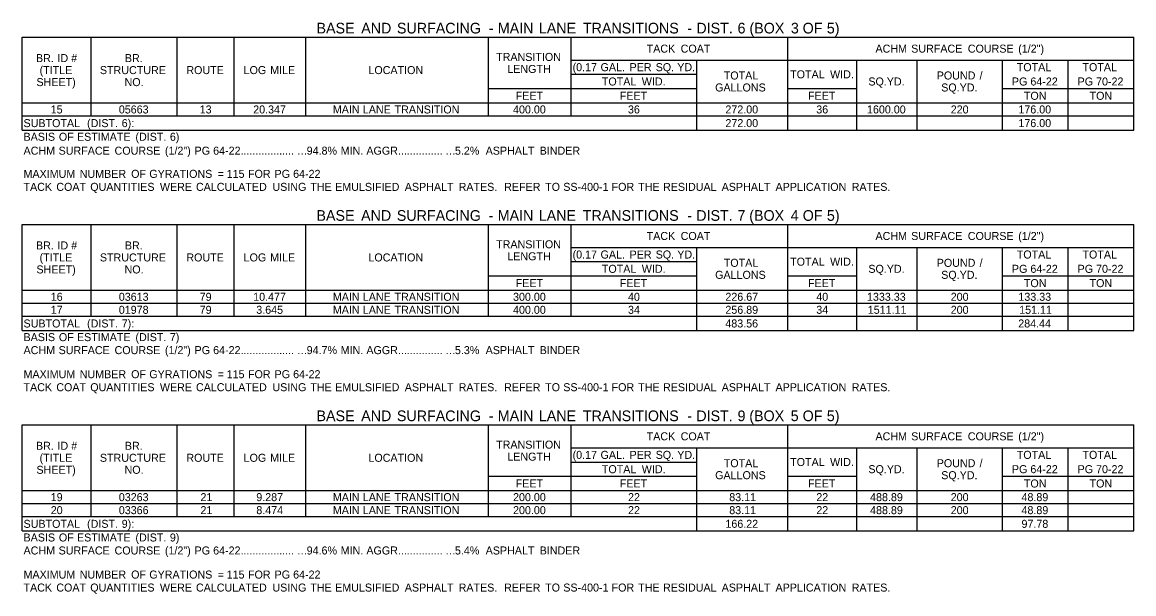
# Model space of a CAD drawing. Extents: x 544255 to 1930787, y -1947044 to 596640.
# Drawn here: x 550281 to 551114, y -1946947 to -1946518 of the extents above; entities that cross this region are included whole.
import ezdxf

# ---------------------------------------------------------------- set-up
doc = ezdxf.new("R2010")
doc.units = 0
doc.layers.add('Default', color=7, linetype='Continuous')

msp = doc.modelspace()

# ---------------------------------------------------------------- linework, layer by layer
at = {"layer": 'Default'}
for p, q in [((550280.78, -1946529.49), (551113.92, -1946529.49)), ((550280.78, -1946599.2), (550280.78, -1946529.49)), ((550332.46, -1946588.47), (550332.46, -1946529.49)), ((550396.81, -1946588.47), (550396.81, -1946529.49)), ((550439.71, -1946588.47), (550439.71, -1946529.49)), ((550493.33, -1946588.47), (550493.33, -1946529.49)), ((550630.32, -1946588.47), (550630.32, -1946529.49)), ((550692.23, -1946588.47), (550692.23, -1946529.49)), ((550692.23, -1946546.55), (550692.23, -1946529.49)), ((550854.57, -1946599.2), (550854.57, -1946529.49)), ((551113.92, -1946599.2), (551113.92, -1946529.49)), ((550692.23, -1946546.55), (551113.92, -1946546.55)), ((550786.32, -1946557.27), (550786.32, -1946546.55)), ((550786.32, -1946599.2), (550786.32, -1946546.55)), ((550906.24, -1946546.55), (550951.58, -1946546.55)), ((550906.24, -1946599.2), (550906.24, -1946546.55)), ((550951.58, -1946599.2), (550951.58, -1946546.55)), ((551015.44, -1946599.2), (551015.44, -1946546.55)), ((551064.68, -1946599.2), (551064.68, -1946546.55)), ((550692.23, -1946557.27), (550786.32, -1946557.27)), ((550630.32, -1946568), (550692.23, -1946568)), ((550630.32, -1946568), (550786.32, -1946568)), ((550786.32, -1946578.72), (550786.32, -1946568)), ((550854.57, -1946568), (550906.24, -1946568)), ((550854.57, -1946578.72), (550854.57, -1946568)), ((550906.24, -1946578.72), (550906.24, -1946568)), ((551015.44, -1946568), (551113.92, -1946568)), ((550280.78, -1946578.72), (550786.32, -1946578.72)), ((550280.78, -1946578.72), (551113.92, -1946578.72)), ((550786.32, -1946578.72), (550906.24, -1946578.72)), ((550906.24, -1946578.72), (551113.92, -1946578.72)), ((550280.78, -1946588.47), (551113.92, -1946588.47)), ((550280.78, -1946599.2), (551113.92, -1946599.2)), ((550280.78, -1946669.89), (551113.92, -1946669.89)), ((550280.78, -1946749.35), (550280.78, -1946669.89)), ((550332.46, -1946738.62), (550332.46, -1946669.89)), ((550396.81, -1946738.62), (550396.81, -1946669.89)), ((550439.71, -1946738.62), (550439.71, -1946669.89)), ((550493.33, -1946738.62), (550493.33, -1946669.89)), ((550630.32, -1946738.62), (550630.32, -1946669.89)), ((550692.23, -1946738.62), (550692.23, -1946669.89)), ((550692.23, -1946686.95), (550692.23, -1946669.89)), ((550854.57, -1946749.35), (550854.57, -1946669.89)), ((551113.92, -1946749.35), (551113.92, -1946669.89)), ((550692.23, -1946686.95), (551113.92, -1946686.95)), ((550786.32, -1946697.67), (550786.32, -1946686.95)), ((550786.32, -1946749.35), (550786.32, -1946686.95)), ((550906.24, -1946686.95), (550951.58, -1946686.95)), ((550906.24, -1946749.35), (550906.24, -1946686.95)), ((550951.58, -1946749.35), (550951.58, -1946686.95)), ((551015.44, -1946749.35), (551015.44, -1946686.95)), ((551064.68, -1946749.35), (551064.68, -1946686.95)), ((550692.23, -1946697.67), (550786.32, -1946697.67)), ((550630.32, -1946708.4), (550692.23, -1946708.4)), ((550630.32, -1946708.4), (550786.32, -1946708.4)), ((550786.32, -1946719.12), (550786.32, -1946708.4)), ((550854.57, -1946708.4), (550906.24, -1946708.4)), ((550854.57, -1946719.12), (550854.57, -1946708.4)), ((550906.24, -1946719.12), (550906.24, -1946708.4)), ((551015.44, -1946708.4), (551113.92, -1946708.4)), ((550280.78, -1946719.12), (550786.32, -1946719.12)), ((550280.78, -1946719.12), (551113.92, -1946719.12)), ((550786.32, -1946719.12), (550906.24, -1946719.12)), ((550906.24, -1946719.12), (551113.92, -1946719.12)), ((550280.78, -1946728.87), (551113.92, -1946728.87)), ((550280.78, -1946738.62), (551113.92, -1946738.62)), ((550280.78, -1946738.62), (551113.92, -1946738.62)), ((550280.78, -1946749.35), (551113.92, -1946749.35)), ((550280.78, -1946820.04), (551113.92, -1946820.04)), ((550280.78, -1946899.5), (550280.78, -1946820.04)), ((550332.46, -1946888.77), (550332.46, -1946820.04)), ((550396.81, -1946888.77), (550396.81, -1946820.04)), ((550439.71, -1946888.77), (550439.71, -1946820.04)), ((550493.33, -1946888.77), (550493.33, -1946820.04)), ((550630.32, -1946888.77), (550630.32, -1946820.04)), ((550692.23, -1946888.77), (550692.23, -1946820.04)), ((550692.23, -1946837.1), (550692.23, -1946820.04)), ((550854.57, -1946899.5), (550854.57, -1946820.04)), ((551113.92, -1946899.5), (551113.92, -1946820.04)), ((550692.23, -1946837.1), (551113.92, -1946837.1)), ((550786.32, -1946847.82), (550786.32, -1946837.1)), ((550786.32, -1946899.5), (550786.32, -1946837.1)), ((550906.24, -1946837.1), (550951.58, -1946837.1)), ((550906.24, -1946899.5), (550906.24, -1946837.1)), ((550951.58, -1946899.5), (550951.58, -1946837.1)), ((551015.44, -1946899.5), (551015.44, -1946837.1)), ((551064.68, -1946899.5), (551064.68, -1946837.1)), ((550692.23, -1946847.82), (550786.32, -1946847.82)), ((550630.32, -1946858.55), (550692.23, -1946858.55)), ((550630.32, -1946858.55), (550786.32, -1946858.55)), ((550786.32, -1946869.27), (550786.32, -1946858.55)), ((550854.57, -1946858.55), (550906.24, -1946858.55)), ((550854.57, -1946869.27), (550854.57, -1946858.55)), ((550906.24, -1946869.27), (550906.24, -1946858.55)), ((551015.44, -1946858.55), (551113.92, -1946858.55)), ((550280.78, -1946869.27), (550786.32, -1946869.27)), ((550280.78, -1946869.27), (551113.92, -1946869.27)), ((550786.32, -1946869.27), (550906.24, -1946869.27)), ((550906.24, -1946869.27), (551113.92, -1946869.27)), ((550280.78, -1946879.02), (551113.92, -1946879.02)), ((550280.78, -1946888.77), (551113.92, -1946888.77)), ((550280.78, -1946888.77), (551113.92, -1946888.77)), ((550280.78, -1946899.5), (551113.92, -1946899.5))]:
    msp.add_line(p, q, dxfattribs=at)

# ---------------------------------------------------------------- texts
for s, height, p in [('BASE', 8, (550501.36, -1946526.66)), (' AND', 8, (550531.87, -1946526.66)), (' SURFACING', 8, (550558.64, -1946526.66)), (' -', 8, (550627.51, -1946526.66)), (' MAIN', 8, (550634.26, -1946526.66)), (' LANE', 8, (550665.03, -1946526.66)), (' TRANSITIONS', 8, (550698.01, -1946526.66)), (' -', 8, (550776.33, -1946526.66)), (' DIST.', 8, (550783.08, -1946526.66)), (' 6', 8, (550813.98, -1946526.66)), (' (BOX', 8, (550822.9, -1946526.66)), (' 3', 8, (550853.94, -1946526.66)), (' OF', 8, (550862.77, -1946526.66)), (' 5)', 8, (550880.88, -1946526.66)), ('BR.', 6, (550291.09, -1946548.1)), (' ID', 6, (550304.96, -1946548.1)), (' #', 6, (550315.25, -1946548.1)), ('BR.', 6, (550357.7, -1946548.1)), ('TRANSITION', 6, (550635.99, -1946547.24)), ('TACK', 6, (550748.81, -1946541.02)), (' COAT', 6, (550772.08, -1946541.02)), ('ACHM', 6, (550920.31, -1946541.02)), (' SURFACE', 6, (550944.86, -1946541.02)), (' COURSE', 6, (550987.3, -1946541.02)), (' (1/2")', 6, (551025.08, -1946541.02)), ('(TITLE', 6, (550293.79, -1946557.1)), ('LENGTH', 6, (550644.36, -1946556.24)), ('(0.17', 6, (550693.3, -1946554.91)), (' GAL.', 6, (550712.03, -1946554.91)), (' PER', 6, (550733.8, -1946554.91)), (' SQ.', 6, (550753.33, -1946554.91)), (' YD.', 6, (550769.52, -1946554.91)), ('TOTAL', 6, (551026.22, -1946554.91)), ('TOTAL', 6, (551075.45, -1946554.91)), ('STRUCTURE', 6, (550338.99, -1946557.1)), ('ROUTE', 6, (550403.79, -1946557.1)), ('LOG', 6, (550446.72, -1946557.1)), (' MILE', 6, (550464.38, -1946557.1)), ('LOCATION', 6, (550540.27, -1946557.1)), ('TOTAL', 6, (550806.6, -1946561.14)), ('TOTAL', 6, (550856.37, -1946560.27)), (' WID.', 6, (550884.06, -1946560.27)), ('POUND', 6, (550966.25, -1946561.14)), (' /', 6, (550996.11, -1946561.14)), ('SHEET)', 6, (550291.46, -1946566.1)), ('NO.', 6, (550357.47, -1946566.1)), ('TOTAL', 6, (550715.24, -1946565.64)), (' WID.', 6, (550742.93, -1946565.64)), ('GALLONS', 6, (550800.15, -1946570.14)), ('SQ.YD.', 6, (550914.99, -1946565.64)), ('SQ.YD.', 6, (550969.59, -1946570.14)), ('PG', 6, (551022.59, -1946565.64)), (' 64-22', 6, (551034.2, -1946565.64)), ('PG', 6, (551071.83, -1946565.64)), (' 70-22', 6, (551083.43, -1946565.64)), ('FEET', 6, (550650.65, -1946576.36)), ('FEET', 6, (550728.65, -1946576.36)), ('FEET', 6, (550869.78, -1946576.36)), ('TON', 6, (551031.55, -1946576.36)), ('TON', 6, (551080.79, -1946576.36)), ('15', 6, (550302.13, -1946586.6)), ('05663', 6, (550353.17, -1946586.6)), ('13', 6, (550413.79, -1946586.6)), ('20.347', 6, (550453.89, -1946586.6)), ('MAIN', 6, (550513.59, -1946586.6)), (' LANE', 6, (550533.86, -1946586.6)), (' TRANSITION', 6, (550557.64, -1946586.6)), ('400.00', 6, (550648.66, -1946586.6)), ('36', 6, (550734.8, -1946586.6)), ('272.00', 6, (550807.83, -1946586.6)), ('36', 6, (550875.94, -1946586.6)), ('1600.00', 6, (550913.97, -1946586.6)), ('220', 6, (550976.72, -1946586.6)), ('176.00', 6, (551027.45, -1946586.6)), ('SUBTOTAL', 6, (550281.76, -1946596.84)), (' (DIST.', 6, (550327.15, -1946596.84)), (' 6):', 6, (550353.12, -1946596.84)), ('272.00', 6, (550807.84, -1946596.84)), ('176.00', 6, (551027.45, -1946596.84)), (' (DIST.', 6, (550363.41, -1946607.07)), (' 6)', 6, (550389.22, -1946607.07)), ('BASIS', 6, (550281.76, -1946607.07)), (' OF', 6, (550306.02, -1946607.07)), (' ESTIMATE', 6, (550319.6, -1946607.07)), ('ACHM', 6, (550281.76, -1946617.5)), (' SURFACE', 6, (550305.81, -1946617.5)), (' COURSE', 6, (550347.76, -1946617.5)), (' (1/2")', 6, (550385.51, -1946617.5)), (' PG', 6, (550407.74, -1946617.5)), (' 64-22..................', 6, (550421.65, -1946617.5)), ('…', 6, (550486.58, -1946617.5)), ('94.8%', 6, (550493.98, -1946617.5)), (' MIN.', 6, (550517.22, -1946617.5)), (' AGGR...............', 6, (550536.51, -1946617.5)), ('…', 6, (550597.71, -1946617.5)), ('5.2%', 6, (550605.11, -1946617.5)), ('  ASPHALT', 6, (550623.69, -1946617.5)), (' BINDER', 6, (550666.39, -1946617.5)), ('MAXIMUM', 6, (550281.76, -1946634.86)), (' NUMBER', 6, (550321.64, -1946634.86)), (' OF', 6, (550360.19, -1946634.86)), (' GYRATIONS', 6, (550373.78, -1946634.86)), (' =', 6, (550425.05, -1946634.86)), (' 115', 6, (550431.8, -1946634.86)), (' FOR', 6, (550447.78, -1946634.86)), (' PG', 6, (550467.69, -1946634.86)), (' 64-22', 6, (550481.6, -1946634.86)), ('TACK', 6, (550281.76, -1946644.61)), (' COAT', 6, (550304.1, -1946644.61)), (' QUANTITIES', 6, (550329.55, -1946644.61)), (' WERE', 6, (550381.75, -1946644.61)), (' CALCULATED', 6, (550408.78, -1946644.61)), (' USING', 6, (550466.1, -1946644.61)), (' THE', 6, (550494.45, -1946644.61)), (' EMULSIFIED', 6, (550513.1, -1946644.61)), (' ASPHALT', 6, (550565.29, -1946644.61)), (' RATES.', 6, (550605.66, -1946644.61)), ('  REFER', 6, (550637.54, -1946644.61)), (' TO', 6, (550670.5, -1946644.61)), (' SS-400-1', 6, (550684.09, -1946644.61)), (' FOR', 6, (550720.29, -1946644.61)), (' THE', 6, (550740.2, -1946644.61)), (' RESIDUAL', 6, (550758.85, -1946644.61)), (' ASPHALT', 6, (550802.81, -1946644.61)), (' APPLICATION', 6, (550843.18, -1946644.61)), (' RATES.', 6, (550900.26, -1946644.61)), ('BASE', 8, (550501.3, -1946667.06)), (' AND', 8, (550531.8, -1946667.06)), (' SURFACING', 8, (550558.57, -1946667.06)), (' MAIN', 8, (550634.19, -1946667.06)), (' LANE', 8, (550664.96, -1946667.06)), (' TRANSITIONS', 8, (550697.94, -1946667.06)), (' DIST.', 8, (550783.01, -1946667.06)), (' 7', 8, (550813.91, -1946667.06)), (' (BOX', 8, (550822.74, -1946667.06)), (' 4', 8, (550853.77, -1946667.06)), (' OF', 8, (550862.83, -1946667.06)), (' 5)', 8, (550880.94, -1946667.06)), (' -', 8, (550627.45, -1946667.06)), (' -', 8, (550776.27, -1946667.06)), ('TACK', 6, (550748.81, -1946681.42)), (' COAT', 6, (550772.08, -1946681.42)), ('ACHM', 6, (550920.31, -1946681.42)), (' SURFACE', 6, (550944.86, -1946681.42)), (' COURSE', 6, (550987.3, -1946681.42)), (' (1/2")', 6, (551025.08, -1946681.42)), ('BR.', 6, (550291.09, -1946688.5)), (' ID', 6, (550304.96, -1946688.5)), (' #', 6, (550315.25, -1946688.5)), ('BR.', 6, (550357.7, -1946688.5)), ('TRANSITION', 6, (550635.99, -1946687.64)), ('(TITLE', 6, (550293.79, -1946697.5)), ('STRUCTURE', 6, (550338.99, -1946697.5)), ('ROUTE', 6, (550403.79, -1946697.5)), ('LOG', 6, (550446.72, -1946697.5)), (' MILE', 6, (550464.38, -1946697.5)), ('LOCATION', 6, (550540.27, -1946697.5)), ('LENGTH', 6, (550644.36, -1946696.64)), ('(0.17', 6, (550693.3, -1946695.31)), (' GAL.', 6, (550712.03, -1946695.31)), (' PER', 6, (550733.8, -1946695.31)), (' SQ.', 6, (550753.33, -1946695.31)), (' YD.', 6, (550769.52, -1946695.31)), ('TOTAL', 6, (551026.22, -1946695.31)), ('TOTAL', 6, (551075.45, -1946695.31)), ('SHEET)', 6, (550291.46, -1946706.5)), ('NO.', 6, (550357.47, -1946706.5)), ('TOTAL', 6, (550715.24, -1946706.04)), (' WID.', 6, (550742.93, -1946706.04)), ('TOTAL', 6, (550806.6, -1946701.54)), ('TOTAL', 6, (550856.37, -1946700.67)), (' WID.', 6, (550884.06, -1946700.67)), ('SQ.YD.', 6, (550914.99, -1946706.04)), ('POUND', 6, (550966.25, -1946701.54)), (' /', 6, (550996.11, -1946701.54)), ('PG', 6, (551022.59, -1946706.04)), (' 64-22', 6, (551034.2, -1946706.04)), ('PG', 6, (551071.83, -1946706.04)), (' 70-22', 6, (551083.43, -1946706.04)), ('GALLONS', 6, (550800.15, -1946710.54)), ('SQ.YD.', 6, (550969.59, -1946710.54)), ('FEET', 6, (550650.65, -1946716.76)), ('FEET', 6, (550728.65, -1946716.76)), ('FEET', 6, (550869.78, -1946716.76)), ('TON', 6, (551031.55, -1946716.76)), ('TON', 6, (551080.79, -1946716.76)), ('16', 6, (550302.15, -1946727)), ('03613', 6, (550353.17, -1946727)), ('79', 6, (550413.78, -1946727)), ('10.477', 6, (550453.89, -1946727)), ('MAIN', 6, (550513.59, -1946727)), (' LANE', 6, (550533.86, -1946727)), (' TRANSITION', 6, (550557.64, -1946727)), ('300.00', 6, (550648.66, -1946727)), ('40', 6, (550734.82, -1946727)), ('226.67', 6, (550807.82, -1946727)), ('40', 6, (550875.95, -1946727)), ('1333.33', 6, (550913.96, -1946727)), ('200', 6, (550976.72, -1946727)), ('133.33', 6, (551027.44, -1946727)), ('17', 6, (550302.15, -1946736.75)), ('01978', 6, (550353.17, -1946736.75)), ('79', 6, (550413.78, -1946736.75)), ('3.645', 6, (550456.2, -1946736.75)), ('MAIN', 6, (550513.59, -1946736.75)), (' LANE', 6, (550533.86, -1946736.75)), (' TRANSITION', 6, (550557.64, -1946736.75)), ('400.00', 6, (550648.66, -1946736.75)), ('34', 6, (550734.82, -1946736.75)), ('256.89', 6, (550807.81, -1946736.75)), ('34', 6, (550875.95, -1946736.75)), ('1511.11', 6, (550914.54, -1946736.75)), ('200', 6, (550976.72, -1946736.75)), ('151.11', 6, (551028.02, -1946736.75)), ('SUBTOTAL', 6, (550281.76, -1946746.99)), (' (DIST.', 6, (550327.15, -1946746.99)), (' 7):', 6, (550353.12, -1946746.99)), ('483.56', 6, (550807.78, -1946746.99)), ('284.44', 6, (551027.34, -1946746.99)), ('BASIS', 6, (550281.76, -1946757.22)), (' OF', 6, (550306.02, -1946757.22)), (' ESTIMATE', 6, (550319.6, -1946757.22)), (' (DIST.', 6, (550363.41, -1946757.22)), (' 7)', 6, (550389.22, -1946757.22)), ('ACHM', 6, (550281.76, -1946766.97)), (' SURFACE', 6, (550305.81, -1946766.97)), (' COURSE', 6, (550347.76, -1946766.97)), (' (1/2")', 6, (550385.51, -1946766.97)), (' PG', 6, (550407.74, -1946766.97)), (' 64-22..................', 6, (550421.65, -1946766.97)), ('…', 6, (550486.58, -1946766.97)), ('94.7%', 6, (550493.98, -1946766.97)), (' MIN.', 6, (550517.22, -1946766.97)), (' AGGR...............', 6, (550536.51, -1946766.97)), ('…', 6, (550597.71, -1946766.97)), ('5.3%', 6, (550605.11, -1946766.97)), ('  ASPHALT', 6, (550623.69, -1946766.97)), (' BINDER', 6, (550666.39, -1946766.97)), ('MAXIMUM', 6, (550281.76, -1946785.01)), (' NUMBER', 6, (550321.64, -1946785.01)), (' OF', 6, (550360.19, -1946785.01)), (' GYRATIONS', 6, (550373.78, -1946785.01)), (' =', 6, (550425.05, -1946785.01)), (' 115', 6, (550431.8, -1946785.01)), (' FOR', 6, (550447.78, -1946785.01)), (' PG', 6, (550467.69, -1946785.01)), (' 64-22', 6, (550481.6, -1946785.01)), ('TACK', 6, (550281.76, -1946794.76)), (' COAT', 6, (550304.1, -1946794.76)), (' QUANTITIES', 6, (550329.55, -1946794.76)), (' WERE', 6, (550381.75, -1946794.76)), (' CALCULATED', 6, (550408.78, -1946794.76)), (' USING', 6, (550466.1, -1946794.76)), (' THE', 6, (550494.45, -1946794.76)), (' EMULSIFIED', 6, (550513.1, -1946794.76)), (' ASPHALT', 6, (550565.29, -1946794.76)), (' RATES.', 6, (550605.66, -1946794.76)), ('  REFER', 6, (550637.54, -1946794.76)), (' TO', 6, (550670.5, -1946794.76)), (' SS-400-1', 6, (550684.09, -1946794.76)), (' FOR', 6, (550720.29, -1946794.76)), (' THE', 6, (550740.2, -1946794.76)), (' RESIDUAL', 6, (550758.85, -1946794.76)), (' ASPHALT', 6, (550802.81, -1946794.76)), (' APPLICATION', 6, (550843.18, -1946794.76)), (' RATES.', 6, (550900.26, -1946794.76)), (' (BOX', 8, (550822.76, -1946817.21)), (' 5)', 8, (550880.89, -1946817.21)), ('BASE', 8, (550501.35, -1946817.21)), (' AND', 8, (550531.86, -1946817.21)), (' SURFACING', 8, (550558.62, -1946817.21)), (' -', 8, (550627.5, -1946817.21)), (' MAIN', 8, (550634.25, -1946817.21)), (' LANE', 8, (550665.01, -1946817.21)), (' TRANSITIONS', 8, (550698, -1946817.21)), (' -', 8, (550776.32, -1946817.21)), (' DIST.', 8, (550783.06, -1946817.21)), (' 9', 8, (550813.97, -1946817.21)), (' 5', 8, (550853.8, -1946817.21)), (' OF', 8, (550862.78, -1946817.21)), ('TACK', 6, (550748.81, -1946831.57)), (' COAT', 6, (550772.08, -1946831.57)), ('ACHM', 6, (550920.31, -1946831.57)), (' SURFACE', 6, (550944.86, -1946831.57)), (' COURSE', 6, (550987.3, -1946831.57)), (' (1/2")', 6, (551025.08, -1946831.57)), ('BR.', 6, (550291.09, -1946838.65)), (' ID', 6, (550304.96, -1946838.65)), (' #', 6, (550315.25, -1946838.65)), ('BR.', 6, (550357.7, -1946838.65)), ('TRANSITION', 6, (550635.99, -1946837.79)), ('(TITLE', 6, (550293.79, -1946847.65)), ('STRUCTURE', 6, (550338.99, -1946847.65)), ('ROUTE', 6, (550403.79, -1946847.65)), ('LOG', 6, (550446.72, -1946847.65)), (' MILE', 6, (550464.38, -1946847.65)), ('LOCATION', 6, (550540.27, -1946847.65)), ('LENGTH', 6, (550644.36, -1946846.79)), ('(0.17', 6, (550693.3, -1946845.46)), (' GAL.', 6, (550712.03, -1946845.46)), (' PER', 6, (550733.8, -1946845.46)), (' SQ.', 6, (550753.33, -1946845.46)), (' YD.', 6, (550769.52, -1946845.46)), ('TOTAL', 6, (551026.22, -1946845.46)), ('TOTAL', 6, (551075.45, -1946845.46)), ('SHEET)', 6, (550291.46, -1946856.65)), ('NO.', 6, (550357.47, -1946856.65)), ('TOTAL', 6, (550715.24, -1946856.19)), (' WID.', 6, (550742.93, -1946856.19)), ('TOTAL', 6, (550806.6, -1946851.69)), ('TOTAL', 6, (550856.37, -1946850.82)), (' WID.', 6, (550884.06, -1946850.82)), ('SQ.YD.', 6, (550914.99, -1946856.19)), ('POUND', 6, (550966.25, -1946851.69)), (' /', 6, (550996.11, -1946851.69)), ('PG', 6, (551022.59, -1946856.19)), (' 64-22', 6, (551034.2, -1946856.19)), ('PG', 6, (551071.83, -1946856.19)), (' 70-22', 6, (551083.43, -1946856.19)), ('GALLONS', 6, (550800.15, -1946860.69)), ('SQ.YD.', 6, (550969.59, -1946860.69)), ('FEET', 6, (550650.65, -1946866.91)), ('FEET', 6, (550728.65, -1946866.91)), ('FEET', 6, (550869.78, -1946866.91)), ('TON', 6, (551031.55, -1946866.91)), ('TON', 6, (551080.79, -1946866.91)), ('19', 6, (550302.14, -1946877.15)), ('03263', 6, (550353.17, -1946877.15)), ('21', 6, (550414.37, -1946877.15)), ('9.287', 6, (550456.22, -1946877.15)), ('MAIN', 6, (550513.59, -1946877.15)), (' LANE', 6, (550533.86, -1946877.15)), (' TRANSITION', 6, (550557.64, -1946877.15)), ('200.00', 6, (550648.66, -1946877.15)), ('22', 6, (550734.84, -1946877.15)), ('83.11', 6, (550810.73, -1946877.15)), ('22', 6, (550875.97, -1946877.15)), ('488.89', 6, (550916.28, -1946877.15)), ('200', 6, (550976.72, -1946877.15)), ('48.89', 6, (551029.76, -1946877.15)), ('20', 6, (550302.16, -1946886.9)), ('03366', 6, (550353.17, -1946886.9)), ('21', 6, (550414.37, -1946886.9)), ('8.474', 6, (550456.24, -1946886.9)), ('MAIN', 6, (550513.59, -1946886.9)), (' LANE', 6, (550533.86, -1946886.9)), (' TRANSITION', 6, (550557.64, -1946886.9)), ('200.00', 6, (550648.66, -1946886.9)), ('22', 6, (550734.84, -1946886.9)), ('83.11', 6, (550810.73, -1946886.9)), ('22', 6, (550875.97, -1946886.9)), ('488.89', 6, (550916.28, -1946886.9)), ('200', 6, (550976.72, -1946886.9)), ('48.89', 6, (551029.76, -1946886.9)), ('SUBTOTAL', 6, (550281.76, -1946897.14)), (' (DIST.', 6, (550327.15, -1946897.14)), (' 9):', 6, (550353.12, -1946897.14)), ('166.22', 6, (550807.84, -1946897.14)), ('97.78', 6, (551029.77, -1946897.14)), ('BASIS', 6, (550281.76, -1946907.37)), (' OF', 6, (550306.02, -1946907.37)), (' ESTIMATE', 6, (550319.6, -1946907.37)), (' (DIST.', 6, (550363.41, -1946907.37)), (' 9)', 6, (550389.22, -1946907.37)), ('ACHM', 6, (550281.76, -1946917.12)), (' SURFACE', 6, (550305.81, -1946917.12)), (' COURSE', 6, (550347.76, -1946917.12)), (' (1/2")', 6, (550385.51, -1946917.12)), (' PG', 6, (550407.74, -1946917.12)), (' 64-22..................', 6, (550421.65, -1946917.12)), ('…', 6, (550486.58, -1946917.12)), ('94.6%', 6, (550493.98, -1946917.12)), (' MIN.', 6, (550517.22, -1946917.12)), (' AGGR...............', 6, (550536.51, -1946917.12)), ('…', 6, (550597.71, -1946917.12)), ('5.4%', 6, (550605.11, -1946917.12)), ('  ASPHALT', 6, (550623.69, -1946917.12)), (' BINDER', 6, (550666.39, -1946917.12)), ('MAXIMUM', 6, (550281.76, -1946935.16)), (' NUMBER', 6, (550321.64, -1946935.16)), (' OF', 6, (550360.19, -1946935.16)), (' GYRATIONS', 6, (550373.78, -1946935.16)), (' =', 6, (550425.05, -1946935.16)), (' 115', 6, (550431.8, -1946935.16)), (' FOR', 6, (550447.78, -1946935.16)), (' PG', 6, (550467.69, -1946935.16)), (' 64-22', 6, (550481.6, -1946935.16)), ('TACK', 6, (550281.76, -1946944.91)), (' COAT', 6, (550304.1, -1946944.91)), (' QUANTITIES', 6, (550329.55, -1946944.91)), (' WERE', 6, (550381.75, -1946944.91)), (' CALCULATED', 6, (550408.78, -1946944.91)), (' USING', 6, (550466.1, -1946944.91)), (' THE', 6, (550494.45, -1946944.91)), (' EMULSIFIED', 6, (550513.1, -1946944.91)), (' ASPHALT', 6, (550565.29, -1946944.91)), (' RATES.', 6, (550605.66, -1946944.91)), ('  REFER', 6, (550637.54, -1946944.91)), (' TO', 6, (550670.5, -1946944.91)), (' SS-400-1', 6, (550684.09, -1946944.91)), (' FOR', 6, (550720.29, -1946944.91)), (' THE', 6, (550740.2, -1946944.91)), (' RESIDUAL', 6, (550758.85, -1946944.91)), (' ASPHALT', 6, (550802.81, -1946944.91)), (' APPLICATION', 6, (550843.18, -1946944.91)), (' RATES.', 6, (550900.26, -1946944.91))]:
    msp.add_text(s, height=height, dxfattribs=at).set_placement(p)

doc.saveas('drawing.dxf')
